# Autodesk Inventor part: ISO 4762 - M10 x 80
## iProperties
Comments: To add or edit properties for Autodesk Inventor files, use iProperties.
Created: 2004-03
Part Number: ISO 4762 - M10 x 80
Vendor: Autodesk Inc.
Document SubType Name: Modeling
Designer: rak
Material: Default
Description: Hexagon Socket Head Cap Screw
Standard: ISO 4762
Size Designation: M10 x 80
Alert: To add or edit properties for Autodesk Inventor files, use iProperties.
Control State: 0
Master: False
Checked Out: False
Shininess: 64.0
Length Units: 11269
Angle Units: 11279
Time Units: 11290
Mass Units: 11283
Length Display Precision: 3
Angle Display Precision: 2
Compacted: True
EGR: 1
Density: 0.0
Volumn: 0.0
Area: 0.0
PropertySet Name: Model Information
Author: rak
Revision Number: 8
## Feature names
1. Body [Revolution]
2. Slot [Extrusion]
3. Fillet1
4. Chamfer1
